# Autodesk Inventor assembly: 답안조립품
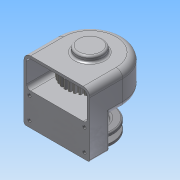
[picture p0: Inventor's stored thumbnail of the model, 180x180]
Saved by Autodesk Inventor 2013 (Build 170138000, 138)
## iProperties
Created: 2015-02
Part Number: 답안조립품
Document SubType Name: Assembly
Designer: Administrator
Author: Administrator
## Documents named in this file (14)
- C:\Documents and Settings\Administrator\바탕 화면\450214V1023\답안조립품.iam
- C:\Documents and Settings\Administrator\바탕 화면\450214V1023\1-본체.ipt
- C:\Documents and Settings\Administrator\바탕 화면\450214V1023\베어링 6001.ipt
- C:\Documents and Settings\Administrator\바탕 화면\450214V1023\축.ipt
- C:\Documents and Settings\Administrator\바탕 화면\450214V1023\키4x4.ipt
- C:\Documents and Settings\Administrator\바탕 화면\450214V1023\키5x5.ipt
- C:\Documents and Settings\Administrator\바탕 화면\450214V1023\5-스퍼기어.ipt
- C:\Documents and Settings\Administrator\바탕 화면\450214V1023\축커버.ipt
- C:\Documents and Settings\Administrator\바탕 화면\450214V1023\오일실.ipt
- C:\Documents and Settings\Administrator\바탕 화면\450214V1023\M3x0.5.ipt
- C:\Documents and Settings\Administrator\바탕 화면\450214V1023\4-V밸트풀리.ipt
- C:\Documents and Settings\Administrator\바탕 화면\450214V1023\와샤.ipt
- C:\Documents and Settings\Administrator\바탕 화면\450214V1023\M5x0.8.ipt
- M5x0.8.ipt
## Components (7 placed, 4 different names)
1. 1-본체:1
2. M3x0.5:1
3. M3x0.5:2
4. M3x0.5:3
5. M3x0.5:4
6. 4-V밸트풀리:1 — 각도:4
7. M5x0.8:1 — 각도:7
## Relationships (2: Angle 2)
- 각도:4 [Angle]: 4-V밸트풀리:1
- 각도:7 [Angle]: M5x0.8:1
